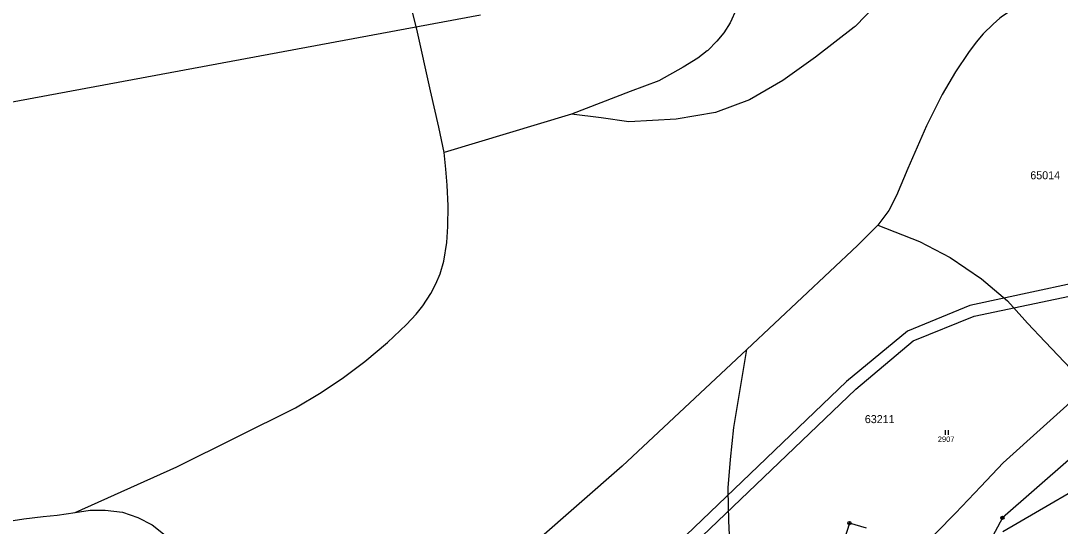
# Model space of a CAD drawing. Extents: x -546762 to -540209, y -1046851 to -1035694.
# Drawn here: x -543169.9 to -542845.1, y -1040001.7 to -1039843.8 of the extents above; entities that cross this region are included whole.
import ezdxf

# ---------------------------------------------------------------- set-up
doc = ezdxf.new("R2010")
doc.units = 0
for name, color, linetype in [('Vrstva 1', 7, 'Continuous'), ('Vrstva 18', 7, 'Continuous'), ('Vrstva 24', 7, 'Continuous'), ('Vrstva 25', 7, 'Continuous'), ('Vrstva 52', 7, 'Continuous'), ('Vrstva 53', 7, 'Continuous')]:
    doc.layers.add(name, color=color, linetype=linetype)

msp = doc.modelspace()

# ---------------------------------------------------------------- linework, layer by layer
at = {"layer": 'Vrstva 1'}
for points in [[(-543026.23, -1039842.05), (-543212.98, -1039876.68)], [(-542821.99, -1039921.7), (-542873.31, -1039932.69)], [(-542871.92, -1039936.07), (-542821.34, -1039925.42)], [(-542873.31, -1039932.69), (-542892.78, -1039940.68)], [(-542890.98, -1039943.72), (-542871.92, -1039936.07)], [(-542892.78, -1039940.68), (-542911.85, -1039956.43)], [(-542908.98, -1039958.9), (-542890.98, -1039943.72)], [(-542911.85, -1039956.43), (-542961.96, -1040004.5)], [(-542959.32, -1040007.09), (-542908.98, -1039958.9)], [(-542842.47, -1039981.08), (-542863.14, -1039999.04)], [(-542827.95, -1039983.03), (-542863, -1040003.43)], [(-542910.93, -1040000.69), (-542913.23, -1040007.85)], [(-542905.58, -1040002.31), (-542910.93, -1040000.69)], [(-542863.14, -1039999.04), (-542873.73, -1040018.81)]]:
    msp.add_lwpolyline(points, dxfattribs=at)
at = {"layer": 'Vrstva 24'}
for centre, radius in [((-542910.93, -1040000.69), 0.5), ((-542910.93, -1040000.69), 0.1), ((-542863.14, -1039999.04), 0.5), ((-542863.14, -1039999.04), 0.1)]:
    msp.add_circle(centre, radius, dxfattribs=at)
at = {"layer": 'Vrstva 25'}
for p, q in [((-542880.95, -1039973.13), (-542880.95, -1039971.63)), ((-542879.95, -1039973.13), (-542879.95, -1039971.63))]:
    msp.add_line(p, q, dxfattribs=at)
at = {"layer": 'Vrstva 52'}
for points in [[(-543037.61, -1039884.89), (-543039.25, -1039876.97), (-543041.8, -1039865.62), (-543046.12, -1039846.34), (-543051.2, -1039825.98), (-543054.19, -1039814.48), (-543055.53, -1039804.16), (-543055.92, -1039797.9), (-543055.98, -1039796.99), (-543055.73, -1039793.45), (-543055.53, -1039790.56), (-543054.79, -1039784.73)], [(-542843.48, -1039835.71), (-542846.26, -1039835.56), (-542849.58, -1039835.76), (-542851.48, -1039836.15), (-542853.97, -1039836.74), (-542855.97, -1039837.66), (-542857.82, -1039838.74), (-542860.65, -1039840.64), (-542863.48, -1039842.59), (-542863.9, -1039842.96), (-542866.01, -1039844.84), (-542869.14, -1039847.86), (-542871.33, -1039850.4), (-542873.77, -1039853.72), (-542877.82, -1039859.72), (-542881.92, -1039866.81), (-542886.87, -1039876.63), (-542892.67, -1039889.87), (-542896.28, -1039898.38), (-542898.67, -1039903.01), (-542902.1, -1039907.64)], [(-542902.45, -1039838.65), (-542909.17, -1039845.53), (-542909.51, -1039845.8), (-542921.57, -1039855.09), (-542931.73, -1039862.41), (-542942.19, -1039868.42), (-542952.79, -1039872.45), (-542965.04, -1039874.55), (-542979.83, -1039875.29), (-542988.49, -1039874.1), (-542997.75, -1039872.9)], [(-542946.19, -1039840.05), (-542948.24, -1039844.41), (-542950.22, -1039847.54), (-542952.36, -1039850.11), (-542955.18, -1039853.01), (-542955.36, -1039853.15), (-542958.33, -1039855.4), (-542962.86, -1039858.3), (-542970.54, -1039862.49), (-542979.42, -1039865.82), (-542997.75, -1039872.9)], [(-542997.75, -1039872.9), (-543037.61, -1039884.89)], [(-543152.9, -1039997.36), (-543121.08, -1039983.16), (-543084, -1039964.67), (-543075.98, -1039959.89), (-543069.07, -1039955.2), (-543062.32, -1039950.24), (-543055.24, -1039944.26), (-543049.35, -1039938.63), (-543046.36, -1039935.47), (-543044.23, -1039932.82), (-543041.75, -1039928.98), (-543040.13, -1039925.9), (-543038.85, -1039922.83), (-543037.66, -1039918.82), (-543036.76, -1039912.99), (-543036.37, -1039908.06), (-543036.29, -1039901.57), (-543036.63, -1039895.08), (-543037.05, -1039890.13), (-543037.61, -1039884.89)], [(-542943.03, -1039946.5), (-542908.38, -1039913.92), (-542902.1, -1039907.64)], [(-542902.1, -1039907.64), (-542889.06, -1039912.68), (-542879.5, -1039917.76), (-542869.64, -1039924.34), (-542861.57, -1039931.22), (-542856.17, -1039937.26), (-542855.32, -1039938.21), (-542849.78, -1039944.07), (-542839.8, -1039954.61), (-542836.51, -1039958.08)], [(-542943.03, -1039946.5), (-542981.91, -1039982.92), (-543008.83, -1040006.45), (-543028.7, -1040024.5), (-543033.44, -1040029.1), (-543042.63, -1040038.01), (-543054.93, -1040051.05), (-543055.32, -1040051.46), (-543059.42, -1040055.83), (-543064.32, -1040061.05), (-543068.77, -1040065.8), (-543079.67, -1040078.36), (-543089.23, -1040090.46), (-543101.48, -1040105.71)], [(-542910.22, -1040029.23), (-542913.06, -1040028.46), (-542917.07, -1040027.78), (-542921.94, -1040027.01), (-542922.43, -1040026.87), (-542926.46, -1040025.73), (-542931.41, -1040024.28), (-542933.53, -1040023.53), (-542936.45, -1040022.49), (-542940.12, -1040020.44), (-542943.11, -1040017.7), (-542945.67, -1040014.2), (-542946.77, -1040011.75), (-542947.2, -1040010.79), (-542947.71, -1040008.33), (-542948.06, -1040006.6), (-542948.48, -1040002.76), (-542948.74, -1039995.84), (-542948.78, -1039989.72), (-542948.09, -1039980.84), (-542947.07, -1039970.85), (-542943.03, -1039946.5)], [(-542890.37, -1040010.39), (-542889.83, -1040009.88), (-542877.8, -1039997.58), (-542869.87, -1039989.23), (-542862.9, -1039981.89), (-542836.66, -1039958.24), (-542836.51, -1039958.08)], [(-543195.32, -1040005.55), (-543189.94, -1040003.76), (-543184.99, -1040002.56), (-543179.01, -1040001.11), (-543173.55, -1040000.09), (-543168.86, -1039999.32), (-543162.88, -1039998.63), (-543158.44, -1039998.21), (-543152.9, -1039997.36)], [(-543152.9, -1039997.36), (-543148.22, -1039996.65), (-543143.44, -1039996.65), (-543138.07, -1039997.25), (-543133.29, -1039998.89), (-543128.81, -1040001.28), (-543124.77, -1040004.42), (-543120.14, -1040008.31), (-543115.81, -1040013.84), (-543112.67, -1040018.92), (-543109.99, -1040025.04), (-543107.6, -1040032.97), (-543107.49, -1040034.18), (-543107, -1040039.54), (-543107.6, -1040045.37), (-543109.01, -1040049.83), (-543109.54, -1040051.5), (-543111.24, -1040054.84), (-543112.82, -1040057.92), (-543113.48, -1040058.99), (-543115.96, -1040063), (-543120.14, -1040067.94), (-543125.23, -1040073.37), (-543147.19, -1040091.48)]]:
    msp.add_lwpolyline(points, dxfattribs=at)

# ---------------------------------------------------------------- texts
at = {"layer": 'Vrstva 18'}
msp.add_text('2907', height=1.7, dxfattribs=at).set_placement((-542883.33, -1039975.34))
at = {"layer": 'Vrstva 53'}
for s, p in [('65014', (-542854.42, -1039893.28)), ('63211', (-542906.13, -1039969.46))]:
    msp.add_text(s, height=2.5, dxfattribs=at).set_placement(p)

doc.saveas('drawing.dxf')
